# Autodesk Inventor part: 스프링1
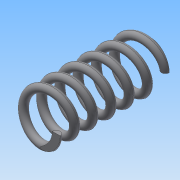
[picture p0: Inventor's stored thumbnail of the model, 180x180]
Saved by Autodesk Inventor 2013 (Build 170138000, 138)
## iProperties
Created: 2015-12
Part Number: 스프링1
Material: 일반
Document SubType Name: Modeling
Designer: Administrator
Density: 1 g/cm^3
Mass: -0.0309105 g
Surface Area: 28.4714 cm^2
Volume: -0.0309105 cm^3
Author: Administrator
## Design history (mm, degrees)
sketch "스케치1"
  geometry: L1 (0, 0)-(8, 0); L2 (0, 0)-(0, 42); L3 (0, 42)-(8, 42); C1 r 1.5 at (8, 0)
  constraints: 6 end point, 2 perpendicular, 1 centre point, 1 coincident, 1 horizontal
  dimensions: "d0" = 8 distance of L1.start L1.end; "d1" = 3 diameter of C1; "d2" = 41.99994 distance of L1.start L2.end (derived); "d4" = 8 distance of L2.end L3.end
feature "코일1" sketch "스케치1" pitch "d5" = 10; turns "d7" = 6; dims "d6" = 41.99994 (= d2), "d8" = 0, angle "d9" = 90 deg, angle "d10" = 90 deg, "d11" = 0, "d12" = 0
sketch "스케치2"
  geometry: L1 (42, 16)-(0, 16); L2 (0, 16)-(0, -16); L3 (0, -16)-(42, -16); L4 (42, -16)-(42, 16); 2 further points
  constraints: 8 end point, 2 parallel, 1 coincident, 1 horizontal, 1 midpoint, 1 perpendicular
  dimensions: "d13" = 32 distance between parallel lines of L3 L1; "d15" = 42 distance between parallel lines of L2 L4 (derived)
extrude "돌출1" sketch "스케치2" stored distance "d16" = 10; taper "d17" = 0 deg
node "솔리드1"
